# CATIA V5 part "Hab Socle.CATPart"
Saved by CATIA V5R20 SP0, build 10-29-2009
Part number: Hab Socle
Bounding box of the stored display mesh (mm): x -30 to 0, y -190 to 101, z -41 to 40
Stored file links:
  D:\Dropbox\IAO_2012\IAO_2012_766_vlaroche\vlaroche\vlaroche\IAO\A rendre\Hab Socle.CATPart
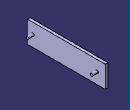
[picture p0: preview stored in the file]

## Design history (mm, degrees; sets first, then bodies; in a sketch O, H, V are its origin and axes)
Body1 (main body)
  Sketch1 on yz-plane, origin (0, 0, 0), H (0, 1, 0), V (0, 0, 1)
    line L1 (-190, 40) -> (101, 40)
    line L2 (101, 40) -> (101, -41)
    line L3 (101, -41) -> (-190, -41)
    line L4 (-190, -41) -> (-190, 40)
    horizontal: L1 H, L3 H
    vertical: L2 V, L4 V
  Pad1: profile Sketch1, direction (1, 0, 0), length -20, opposite side length 30
  Sketch2 on end face of Pad1, origin (-20, 0, 0), H (0, 1, 0), V (0, 0, 1)
    circle A1 centre (-169.4932, 0.0258) radius 5
    circle A2 centre (70.3557, 0.1873) radius 5
    radius A1 = 5
    radius A2 = 5
  Pad2: profile Sketch2, direction (1, 0, 0), length 20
